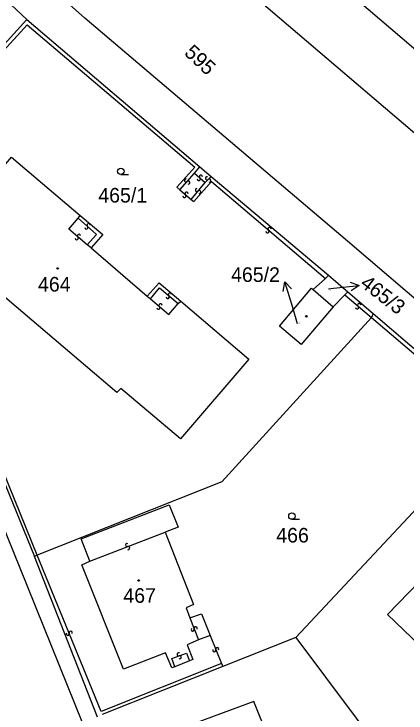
# Model space of a CAD drawing. Extents: x -600391 to -599491, y -1160176 to -1159402.
# Drawn here: x -599837.9 to -599792.2, y -1160042.2 to -1159960.8 of the extents above; entities that cross this region are included whole.
import ezdxf

# ---------------------------------------------------------------- set-up
doc = ezdxf.new("R2010")
doc.units = 0
for name, color, linetype in [('Level 1', 7, 'Continuous'), ('Level 13', 7, 'Continuous'), ('Level 3', 7, 'Continuous'), ('Level 4', 7, 'Continuous'), ('Level 5', 7, 'Continuous'), ('Level 57', 7, 'Continuous')]:
    doc.layers.add(name, color=color, linetype=linetype)

msp = doc.modelspace()

# ---------------------------------------------------------------- linework, layer by layer
at = {"layer": 'Level 1'}
for points in [[(-599773.09, -1160009.38), (-599799.04, -1159987.23), (-599829.62, -1159961.28), (-599837.47, -1159954.27), (-599840.96, -1159951.06), (-599849.35, -1159942.91), (-599851.83, -1159940.43), (-599873.22, -1159917.84), (-599880.94, -1159909.13), (-599886.42, -1159902.9), (-599888.35, -1159901.21), (-599897.08, -1159890.32), (-599918.8, -1159863.43), (-599945.39, -1159830.39)], [(-599707.8, -1160039.08), (-599761.26, -1159990.41), (-599822.74, -1159937.99), (-599833.95, -1159928.46)], [(-599842.97, -1159928.9), (-599830.58, -1159941.08), (-599767.82, -1159994.56)], [(-599773.09, -1160009.38), (-599799.04, -1159987.23), (-599829.62, -1159961.28), (-599837.47, -1159954.27), (-599840.96, -1159951.06)], [(-599846.4, -1159952.01), (-599836.35, -1159961.44)], [(-599836.35, -1159961.44), (-599853.38, -1159980.13), (-599835.49, -1160023.94)], [(-599836.35, -1159961.44), (-599816.21, -1159978.6)], [(-599818.44, -1159994.22), (-599810.51, -1160000.98), (-599818.49, -1160010.25), (-599825.44, -1160004.41), (-599825.9, -1160004.85), (-599839.43, -1159993.35), (-599839.05, -1159992.87), (-599846.11, -1159986.79), (-599838.15, -1159977.46), (-599830.14, -1159984.27)], [(-599816.21, -1159978.6), (-599814.89, -1159979.7)], [(-599814.89, -1159979.7), (-599801.26, -1159991.22)], [(-599830.14, -1159984.27), (-599827.53, -1159986.47), (-599828.89, -1159988.04)], [(-599828.89, -1159988.04), (-599822.35, -1159993.63)], [(-599801.26, -1159991.22), (-599801.58, -1159991.6)], [(-599801.26, -1159991.22), (-599799, -1159993.13)], [(-599822.35, -1159993.63), (-599820.97, -1159992.1), (-599818.44, -1159994.22)], [(-599801.58, -1159991.6), (-599803.03, -1159992.88)], [(-599800.7, -1159994.88), (-599804.44, -1159999.28), (-599806.96, -1159997.15), (-599803.22, -1159992.72), (-599803.03, -1159992.88)], [(-599803.03, -1159992.88), (-599800.7, -1159994.88)], [(-599799.33, -1159993.51), (-599800.7, -1159994.88)], [(-599799, -1159993.13), (-599799.33, -1159993.51)], [(-599799, -1159993.13), (-599796.03, -1159995.65)], [(-599796.25, -1159996.13), (-599813.68, -1160015.27), (-599835.15, -1160023.79)], [(-599796.03, -1159995.65), (-599796.25, -1159996.13)], [(-599796.03, -1159995.65), (-599781.39, -1160008.18)], [(-599781.71, -1160008.48), (-599805.03, -1160033.37)], [(-599829.02, -1160024.48), (-599830.02, -1160021.9), (-599819.78, -1160017.93), (-599818.76, -1160020.55), (-599820.24, -1160021.12)], [(-599820.24, -1160021.12), (-599816.96, -1160029.52), (-599817.81, -1160029.92), (-599817.38, -1160031.1)], [(-599778.18, -1160029.05), (-599785.73, -1160021.79), (-599794.37, -1160030.71), (-599787.75, -1160037.05), (-599788.13, -1160037.52), (-599775.25, -1160049.74), (-599774.87, -1160049.34), (-599768.24, -1160055.58), (-599759.67, -1160046.66), (-599767.09, -1160039.54)], [(-599835.15, -1160023.79), (-599835.49, -1160023.94)], [(-599828.12, -1160042.64), (-599835.49, -1160023.94)], [(-599819.14, -1160036.79), (-599819.49, -1160036.91), (-599820.22, -1160035.17), (-599825.1, -1160037.06), (-599829.97, -1160024.9), (-599829.02, -1160024.48)], [(-599817.38, -1160031.1), (-599816.01, -1160030.61), (-599815.03, -1160033.15)], [(-599815.03, -1160033.15), (-599816.37, -1160033.64)], [(-599805.03, -1160033.37), (-599813.56, -1160036.75)], [(-599805.03, -1160033.37), (-599787.56, -1160056.76)], [(-599816.37, -1160033.64), (-599817.71, -1160034.22), (-599817.04, -1160035.92), (-599817.42, -1160036.09)], [(-599813.56, -1160036.75), (-599827.58, -1160042.35)], [(-599817.42, -1160036.09), (-599819.14, -1160036.79)], [(-599804.86, -1160053.46), (-599809.93, -1160040.82), (-599819.5, -1160044.36)]]:
    msp.add_lwpolyline(points, dxfattribs=at)
at = {"layer": 'Level 13'}
for centre, start, end in [((-599816.343, -1159980.017), 175.35173, 47.94173), ((-599816.096, -1159979.744), 355.56618, 227.66418), ((-599815.371, -1159979.93), 83.16846, 315.26646), ((-599817.828, -1159980.187), 86.10413, 318.20213), ((-599817.552, -1159980.432), 265.88968, 138.47968), ((-599815.109, -1159980.189), 262.954, 135.544), ((-599817.769, -1159981.71), 357.05863, 229.15663), ((-599816.561, -1159981.301), 87.91042, 320.00841), ((-599816.278, -1159981.538), 267.69596, 140.28596), ((-599818.01, -1159981.99), 176.84418, 49.43418), ((-599829.432, -1159985.657), 175.70806, 48.29806), ((-599829.187, -1159985.383), 355.92251, 228.02051), ((-599808.34, -1159986.1), 176.79249, 49.38249), ((-599808.099, -1159985.821), 357.00694, 229.10494), ((-599830.541, -1159986.899), 176.99266, 49.09065), ((-599830.3, -1159986.62), 356.7782, 229.3682), ((-599819.958, -1159993.731), 177.42999, 50.01999), ((-599819.721, -1159993.449), 357.64445, 229.74245), ((-599820.799, -1159994.721), 357.01601, 229.114), ((-599797.669, -1159994.681), 356.9866, 229.0846), ((-599821.04, -1159995), 176.80155, 49.39155), ((-599797.91, -1159994.96), 176.77215, 49.36215), ((-599824.694, -1160022.627), 58.31398, 290.41198), ((-599824.565, -1160022.972), 238.09952, 110.68952), ((-599831.259, -1160032.811), 329.40362, 201.99362), ((-599817.051, -1160032.437), 148.84292, 21.43292), ((-599816.708, -1160032.303), 329.05737, 201.15537), ((-599831.601, -1160032.948), 149.61808, 21.71608), ((-599818.694, -1160035.327), 58.07466, 290.17266), ((-599814.541, -1160034.849), 149.263, 21.853), ((-599814.198, -1160034.712), 329.47745, 201.57545), ((-599818.566, -1160035.672), 237.86021, 110.45021)]:
    msp.add_arc(centre, 0.184, start, end, dxfattribs=at)
at = {"layer": 'Level 3'}
for points in [[(-599846.4, -1159952.01), (-599848.08, -1159953.82), (-599859.23, -1159965.79), (-599859.58, -1159966.58), (-599859.93, -1159967.38), (-599860.05, -1159968.25), (-599859.84, -1159969.13), (-599859.47, -1159970.12), (-599859.1, -1159971.11), (-599852.79, -1159986.79), (-599837.18, -1160025.28), (-599821.6, -1160063.84), (-599805.47, -1160103.79), (-599793.95, -1160133.25), (-599793.45, -1160134.12), (-599792.68, -1160134.75), (-599791.97, -1160134.96), (-599791.42, -1160135), (-599790.84, -1160134.89)], [(-599835.15, -1160023.79), (-599852.87, -1159980.19), (-599836.32, -1159962.05), (-599816.82, -1159978.63), (-599818.91, -1159980.97), (-599818.55, -1159981.29)], [(-599816.83, -1159979.33), (-599816.21, -1159978.6)], [(-599818.55, -1159981.29), (-599816.83, -1159979.33)], [(-599816.83, -1159979.33), (-599815.6, -1159980.43)], [(-599815.6, -1159980.43), (-599814.89, -1159979.7)], [(-599817.23, -1159982.41), (-599816.91, -1159982.64), (-599814.85, -1159980.32), (-599801.58, -1159991.6)], [(-599817.23, -1159982.41), (-599815.6, -1159980.43)], [(-599818.55, -1159981.29), (-599817.23, -1159982.41)], [(-599829.35, -1159987.67), (-599831.49, -1159985.85), (-599830.38, -1159984.57)], [(-599830.38, -1159984.57), (-599830.14, -1159984.27)], [(-599830.38, -1159984.57), (-599828.24, -1159986.46), (-599829.35, -1159987.67)], [(-599828.89, -1159988.04), (-599829.35, -1159987.67)], [(-599821.98, -1159993.96), (-599820.93, -1159992.68), (-599818.74, -1159994.5)], [(-599822.35, -1159993.63), (-599821.98, -1159993.96)], [(-599799.33, -1159993.51), (-599796.25, -1159996.13)], [(-599821.98, -1159993.96), (-599819.85, -1159995.77), (-599818.74, -1159994.5)], [(-599818.74, -1159994.5), (-599818.44, -1159994.22)], [(-599796.25, -1159996.13), (-599781.71, -1160008.48)], [(-599829.02, -1160024.48), (-599820.24, -1160021.12)], [(-599813.71, -1160036.4), (-599827.71, -1160041.98), (-599835.15, -1160023.79)], [(-599817.38, -1160031.1), (-599816.37, -1160033.64)], [(-599815.03, -1160033.15), (-599813.71, -1160036.4)], [(-599819.14, -1160036.79), (-599819.49, -1160035.83), (-599817.77, -1160035.18), (-599817.42, -1160036.09)], [(-599813.71, -1160036.4), (-599813.56, -1160036.75)]]:
    msp.add_lwpolyline(points, dxfattribs=at)
at = {"layer": 'Level 5'}
for p, q in [((-599825.42, -1159979.49), (-599824.545, -1159979.49)), ((-599805.5, -1160019.62), (-599804.625, -1160019.62))]:
    msp.add_line(p, q, dxfattribs=at)
for centre, radius in [((-599825.42, -1159979.115), 0.375), ((-599832.78, -1159990.42), 0.09), ((-599832.78, -1159990.42), 0.0521), ((-599803.82, -1159995.99), 0.09), ((-599803.82, -1159995.99), 0.0521), ((-599805.5, -1160019.245), 0.375), ((-599823.34, -1160026.74), 0.09), ((-599823.34, -1160026.74), 0.0521)]:
    msp.add_circle(centre, radius, dxfattribs=at)
at = {"layer": 'Level 57'}
for p, q in [((-599805.443, -1159994.861), (-599806.314, -1159991.99)), ((-599801.25, -1159992.8), (-599800.647, -1159992.734)), ((-599800.647, -1159992.734), (-599797.665, -1159992.41)), ((-599804.84, -1159996.85), (-599805.443, -1159994.861))]:
    msp.add_line(p, q, dxfattribs=at)
for points in [[(-599806.502, -1159993.092), (-599806.314, -1159991.99), (-599805.545, -1159992.802)], [(-599798.713, -1159992.021), (-599797.665, -1159992.41), (-599798.605, -1159993.015)]]:
    msp.add_lwpolyline(points, dxfattribs=at)

# ---------------------------------------------------------------- texts
at = {"layer": 'Level 4'}
for s, height, rotation, p in [('595', 1.7, 316.8, (-599818.137, -1159965.453)), ('465/3', 0.1, 322.42194, (-599801.25, -1159992.8))]:
    msp.add_text(s, height=height, rotation=rotation, dxfattribs=at).set_placement(p)
for s, height, p in [('465/1', 1.7, (-599828.044, -1159982.75)), ('464', 1.7, (-599835.064, -1159993.11)), ('465/2', 0.1, (-599804.84, -1159996.85)), ('466', 1.7, (-599807.324, -1160022.32)), ('467', 1.7, (-599825.129, -1160029.34))]:
    msp.add_text(s, height=height, dxfattribs=at).set_placement(p)
at = {"layer": 'Level 57'}
msp.add_text('465/2', height=1.7, dxfattribs=at).set_placement((-599812.586, -1159991.99))
msp.add_text('465/3', height=1.7, rotation=322.42194, dxfattribs=at).set_placement((-599797.664, -1159992.411))

doc.saveas('drawing.dxf')
